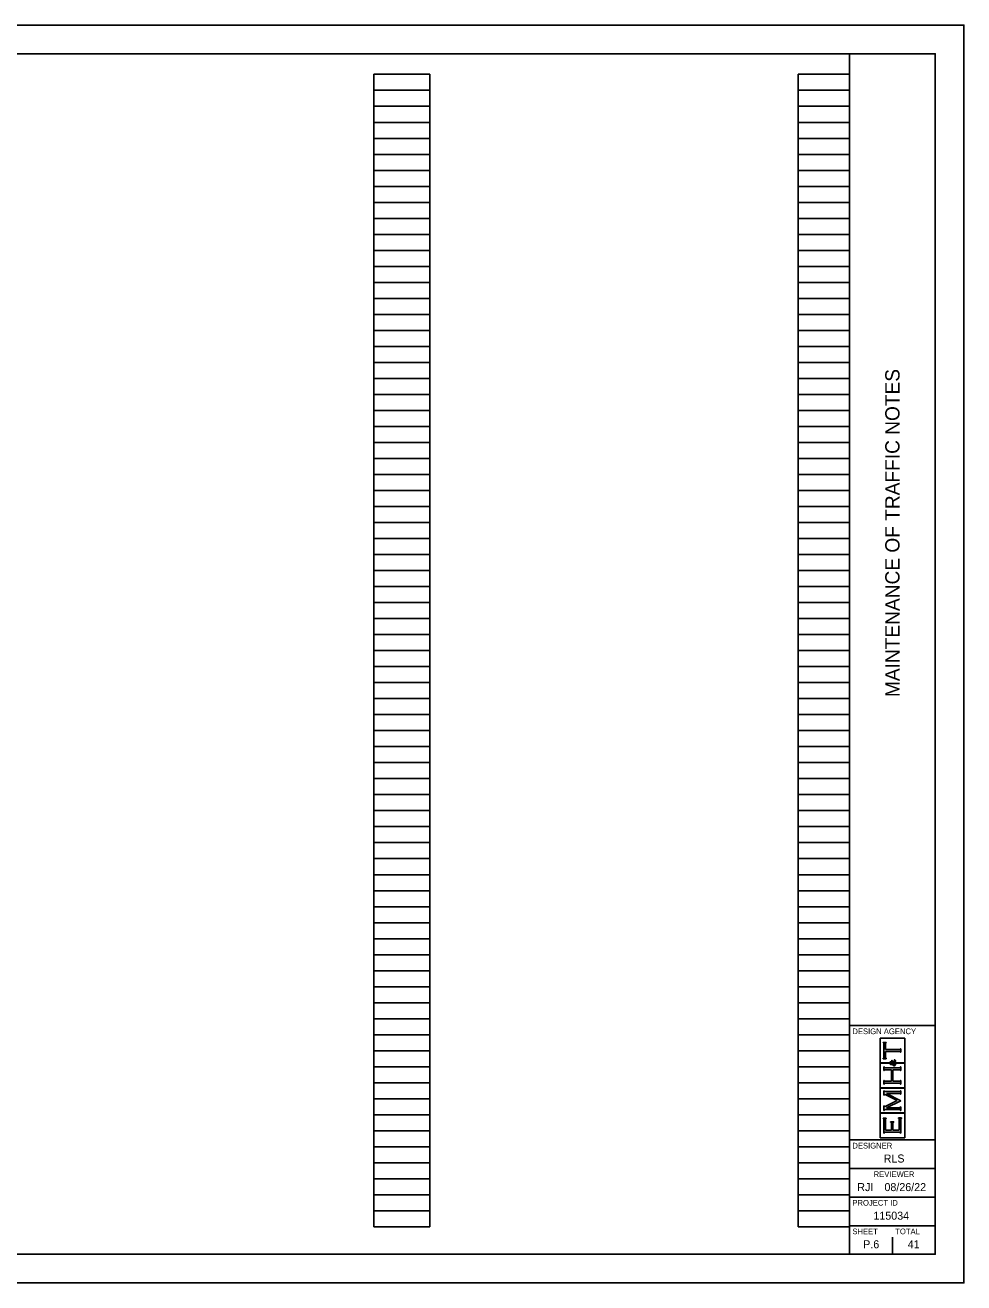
# Model space of a CAD drawing. Extents: x 0 to 34, y 0 to 22.
# Drawn here: x 17.58 to 34, y 0 to 22 of the extents above; entities that cross this region are included whole.
import ezdxf

# ---------------------------------------------------------------- set-up
doc = ezdxf.new("R2010")
doc.units = 0
for name, color, linetype in [('SH_Border', 7, 'Continuous'), ('SH_Cut_Line', 7, 'Continuous'), ('SH_Data', 7, 'Continuous')]:
    doc.layers.add(name, color=color, linetype=linetype)

msp = doc.modelspace()

# ---------------------------------------------------------------- linework, layer by layer
at = {"layer": 'SH_Border'}
for p, q in [((32, 0.5), (32, 21.5)), ((32, 4.5), (33.5, 4.5)), ((32, 2.5), (33.5, 2.5)), ((32, 2), (33.5, 2)), ((32, 1.5), (33.5, 1.5)), ((32, 1), (33.5, 1))]:
    msp.add_line(p, q, dxfattribs=at)
msp.add_lwpolyline([(1.5, 21.5), (33.5, 21.5), (33.5, 0.5), (1.5, 0.5)], close=True, dxfattribs=at)
at = {"layer": 'SH_Cut_Line'}
msp.add_lwpolyline([(0, 0), (34, 0), (34, 22), (0, 22)], close=True, dxfattribs=at)
at = {"layer": 'SH_Data'}
for p, q in [((23.68, 0.98), (23.68, 21.14)), ((23.68, 21.14), (24.66, 21.14)), ((24.66, 0.98), (24.66, 21.14)), ((31.1, 0.98), (31.1, 21.14)), ((31.1, 21.14), (32, 21.14)), ((32, 0.98), (32, 21.14)), ((23.68, 20.86), (24.66, 20.86)), ((31.1, 20.86), (32, 20.86)), ((23.68, 20.58), (24.66, 20.58)), ((31.1, 20.58), (32, 20.58)), ((23.68, 20.3), (24.66, 20.3)), ((31.1, 20.3), (32, 20.3)), ((23.68, 20.02), (24.66, 20.02)), ((31.1, 20.02), (32, 20.02)), ((23.68, 19.74), (24.66, 19.74)), ((31.1, 19.74), (32, 19.74)), ((23.68, 19.46), (24.66, 19.46)), ((31.1, 19.46), (32, 19.46)), ((23.68, 19.18), (24.66, 19.18)), ((31.1, 19.18), (32, 19.18)), ((23.68, 18.9), (24.66, 18.9)), ((31.1, 18.9), (32, 18.9)), ((23.68, 18.62), (24.66, 18.62)), ((31.1, 18.62), (32, 18.62)), ((23.68, 18.34), (24.66, 18.34)), ((31.1, 18.34), (32, 18.34)), ((23.68, 18.06), (24.66, 18.06)), ((31.1, 18.06), (32, 18.06)), ((23.68, 17.78), (24.66, 17.78)), ((31.1, 17.78), (32, 17.78)), ((23.68, 17.5), (24.66, 17.5)), ((31.1, 17.5), (32, 17.5)), ((23.68, 17.22), (24.66, 17.22)), ((31.1, 17.22), (32, 17.22)), ((23.68, 16.94), (24.66, 16.94)), ((31.1, 16.94), (32, 16.94)), ((23.68, 16.66), (24.66, 16.66)), ((31.1, 16.66), (32, 16.66)), ((23.68, 16.38), (24.66, 16.38)), ((31.1, 16.38), (32, 16.38)), ((23.68, 16.1), (24.66, 16.1)), ((31.1, 16.1), (32, 16.1)), ((23.68, 15.82), (24.66, 15.82)), ((31.1, 15.82), (32, 15.82)), ((23.68, 15.54), (24.66, 15.54)), ((31.1, 15.54), (32, 15.54)), ((23.68, 15.26), (24.66, 15.26)), ((31.1, 15.26), (32, 15.26)), ((23.68, 14.98), (24.66, 14.98)), ((31.1, 14.98), (32, 14.98)), ((23.68, 14.7), (24.66, 14.7)), ((31.1, 14.7), (32, 14.7)), ((23.68, 14.42), (24.66, 14.42)), ((31.1, 14.42), (32, 14.42)), ((23.68, 14.14), (24.66, 14.14)), ((31.1, 14.14), (32, 14.14)), ((23.68, 13.86), (24.66, 13.86)), ((31.1, 13.86), (32, 13.86)), ((23.68, 13.58), (24.66, 13.58)), ((31.1, 13.58), (32, 13.58)), ((23.68, 13.3), (24.66, 13.3)), ((31.1, 13.3), (32, 13.3)), ((23.68, 13.02), (24.66, 13.02)), ((31.1, 13.02), (32, 13.02)), ((23.68, 12.74), (24.66, 12.74)), ((31.1, 12.74), (32, 12.74)), ((23.68, 12.46), (24.66, 12.46)), ((31.1, 12.46), (32, 12.46)), ((23.68, 12.18), (24.66, 12.18)), ((31.1, 12.18), (32, 12.18)), ((23.68, 11.9), (24.66, 11.9)), ((31.1, 11.9), (32, 11.9)), ((23.68, 11.62), (24.66, 11.62)), ((31.1, 11.62), (32, 11.62)), ((23.68, 11.34), (24.66, 11.34)), ((31.1, 11.34), (32, 11.34)), ((23.68, 11.06), (24.66, 11.06)), ((31.1, 11.06), (32, 11.06)), ((23.68, 10.78), (24.66, 10.78)), ((31.1, 10.78), (32, 10.78)), ((23.68, 10.5), (24.66, 10.5)), ((31.1, 10.5), (32, 10.5)), ((23.68, 10.22), (24.66, 10.22)), ((31.1, 10.22), (32, 10.22)), ((23.68, 9.94), (24.66, 9.94)), ((31.1, 9.94), (32, 9.94)), ((23.68, 9.66), (24.66, 9.66)), ((31.1, 9.66), (32, 9.66)), ((23.68, 9.38), (24.66, 9.38)), ((31.1, 9.38), (32, 9.38)), ((23.68, 9.1), (24.66, 9.1)), ((31.1, 9.1), (32, 9.1)), ((23.68, 8.82), (24.66, 8.82)), ((31.1, 8.82), (32, 8.82)), ((23.68, 8.54), (24.66, 8.54)), ((31.1, 8.54), (32, 8.54)), ((23.68, 8.26), (24.66, 8.26)), ((31.1, 8.26), (32, 8.26)), ((23.68, 7.98), (24.66, 7.98)), ((31.1, 7.98), (32, 7.98)), ((23.68, 7.7), (24.66, 7.7)), ((31.1, 7.7), (32, 7.7)), ((23.68, 7.42), (24.66, 7.42)), ((31.1, 7.42), (32, 7.42)), ((23.68, 7.14), (24.66, 7.14)), ((31.1, 7.14), (32, 7.14)), ((23.68, 6.86), (24.66, 6.86)), ((31.1, 6.86), (32, 6.86)), ((23.68, 6.58), (24.66, 6.58)), ((31.1, 6.58), (32, 6.58)), ((23.68, 6.3), (24.66, 6.3)), ((31.1, 6.3), (32, 6.3)), ((23.68, 6.02), (24.66, 6.02)), ((31.1, 6.02), (32, 6.02)), ((23.68, 5.74), (24.66, 5.74)), ((31.1, 5.74), (32, 5.74)), ((23.68, 5.46), (24.66, 5.46)), ((31.1, 5.46), (32, 5.46)), ((23.68, 5.18), (24.66, 5.18)), ((31.1, 5.18), (32, 5.18)), ((23.68, 4.9), (24.66, 4.9)), ((31.1, 4.9), (32, 4.9)), ((23.68, 4.62), (24.66, 4.62)), ((31.1, 4.62), (32, 4.62)), ((23.68, 4.34), (24.66, 4.34)), ((31.1, 4.34), (32, 4.34)), ((32.966, 4.28), (32.534, 4.28)), ((32.534, 4.28), (32.534, 3.848)), ((32.588, 4.199), (32.588, 4.206)), ((32.588, 4.206), (32.644, 4.206)), ((32.594, 4.198), (32.588, 4.199)), ((32.598, 4.196), (32.594, 4.198)), ((32.599, 4.194), (32.598, 4.196)), ((32.601, 4.191), (32.599, 4.194)), ((32.602, 4.187), (32.601, 4.191)), ((32.602, 4.181), (32.602, 4.187)), ((32.602, 3.947), (32.602, 4.181)), ((32.632, 4.191), (32.631, 4.187)), ((32.631, 4.187), (32.631, 4.181)), ((32.631, 4.181), (32.631, 4.081)), ((32.633, 4.194), (32.632, 4.191)), ((32.635, 4.196), (32.633, 4.194)), ((32.639, 4.198), (32.635, 4.196)), ((32.644, 4.199), (32.639, 4.198)), ((32.644, 4.206), (32.644, 4.199)), ((32.966, 3.848), (32.966, 4.28)), ((23.68, 4.06), (24.66, 4.06)), ((31.1, 4.06), (32, 4.06)), ((32.631, 4.081), (32.872, 4.081)), ((32.872, 4.047), (32.631, 4.047)), ((32.631, 4.047), (32.631, 3.947)), ((32.872, 4.081), (32.878, 4.081)), ((32.878, 4.047), (32.872, 4.047)), ((32.878, 4.081), (32.882, 4.082)), ((32.883, 4.046), (32.878, 4.047)), ((32.882, 4.082), (32.885, 4.084)), ((32.885, 4.044), (32.883, 4.046)), ((32.885, 4.084), (32.887, 4.085)), ((32.888, 4.042), (32.885, 4.044)), ((32.887, 4.085), (32.889, 4.089)), ((32.889, 4.039), (32.888, 4.042)), ((32.889, 4.089), (32.891, 4.095)), ((32.891, 4.033), (32.889, 4.039)), ((32.891, 4.095), (32.898, 4.095)), ((32.898, 4.033), (32.891, 4.033)), ((32.898, 4.095), (32.898, 4.033)), ((23.68, 3.78), (24.66, 3.78)), ((31.1, 3.78), (32, 3.78)), ((32.534, 3.848), (32.693, 3.848)), ((32.693, 3.842), (32.534, 3.842)), ((32.534, 3.842), (32.534, 3.41)), ((32.588, 3.928), (32.594, 3.93)), ((32.588, 3.921), (32.588, 3.928)), ((32.644, 3.921), (32.588, 3.921)), ((32.594, 3.93), (32.598, 3.932)), ((32.598, 3.932), (32.599, 3.934)), ((32.599, 3.934), (32.601, 3.937)), ((32.601, 3.937), (32.602, 3.941)), ((32.602, 3.941), (32.602, 3.947)), ((32.602, 3.714), (32.602, 3.776)), ((32.602, 3.776), (32.609, 3.776)), ((32.609, 3.776), (32.611, 3.77)), ((32.611, 3.77), (32.612, 3.766)), ((32.612, 3.766), (32.615, 3.765)), ((32.615, 3.765), (32.617, 3.763)), ((32.617, 3.763), (32.622, 3.762)), ((32.622, 3.762), (32.628, 3.762)), ((32.628, 3.762), (32.872, 3.762)), ((32.631, 3.947), (32.631, 3.941)), ((32.631, 3.941), (32.632, 3.937)), ((32.632, 3.937), (32.633, 3.934)), ((32.633, 3.934), (32.635, 3.932)), ((32.635, 3.932), (32.639, 3.93)), ((32.639, 3.93), (32.644, 3.928)), ((32.644, 3.928), (32.644, 3.921)), ((32.693, 3.848), (32.693, 3.842)), ((32.701, 3.852), (32.703, 3.857)), ((32.701, 3.846), (32.701, 3.852)), ((32.701, 3.84), (32.701, 3.846)), ((32.703, 3.835), (32.701, 3.84)), ((32.703, 3.857), (32.706, 3.861)), ((32.706, 3.83), (32.703, 3.835)), ((32.706, 3.861), (32.71, 3.864)), ((32.707, 3.852), (32.706, 3.849)), ((32.706, 3.849), (32.706, 3.846)), ((32.706, 3.846), (32.706, 3.842)), ((32.706, 3.842), (32.708, 3.839)), ((32.71, 3.824), (32.706, 3.83)), ((32.71, 3.854), (32.707, 3.852)), ((32.708, 3.839), (32.711, 3.837)), ((32.71, 3.864), (32.714, 3.866)), ((32.712, 3.856), (32.71, 3.854)), ((32.717, 3.821), (32.71, 3.824)), ((32.711, 3.837), (32.714, 3.835)), ((32.715, 3.857), (32.712, 3.856)), ((32.714, 3.866), (32.719, 3.866)), ((32.714, 3.835), (32.716, 3.834)), ((32.718, 3.857), (32.715, 3.857)), ((32.716, 3.834), (32.719, 3.834)), ((32.725, 3.821), (32.717, 3.821)), ((32.723, 3.857), (32.718, 3.857)), ((32.719, 3.866), (32.724, 3.866)), ((32.719, 3.834), (32.722, 3.834)), ((32.722, 3.834), (32.724, 3.834)), ((32.727, 3.856), (32.723, 3.857)), ((32.724, 3.866), (32.728, 3.864)), ((32.724, 3.834), (32.727, 3.835)), ((32.728, 3.821), (32.725, 3.821)), ((32.73, 3.853), (32.727, 3.856)), ((32.727, 3.835), (32.73, 3.836)), ((32.728, 3.864), (32.732, 3.861)), ((32.731, 3.822), (32.728, 3.821)), ((32.734, 3.85), (32.73, 3.853)), ((32.73, 3.836), (32.734, 3.837)), ((32.734, 3.822), (32.731, 3.822)), ((32.732, 3.861), (32.736, 3.857)), ((32.737, 3.845), (32.734, 3.85)), ((32.734, 3.837), (32.74, 3.839)), ((32.737, 3.823), (32.734, 3.822)), ((32.736, 3.857), (32.74, 3.851)), ((32.74, 3.839), (32.737, 3.845)), ((32.741, 3.825), (32.737, 3.823)), ((32.738, 3.867), (32.738, 3.898)), ((32.738, 3.898), (32.741, 3.898)), ((32.741, 3.867), (32.738, 3.867)), ((32.74, 3.851), (32.745, 3.842)), ((32.741, 3.898), (32.741, 3.894)), ((32.741, 3.894), (32.742, 3.891)), ((32.742, 3.871), (32.741, 3.869)), ((32.741, 3.869), (32.741, 3.867)), ((32.746, 3.827), (32.741, 3.825)), ((32.742, 3.891), (32.744, 3.889)), ((32.743, 3.872), (32.742, 3.871)), ((32.745, 3.873), (32.743, 3.872)), ((32.744, 3.889), (32.745, 3.887)), ((32.745, 3.887), (32.75, 3.883)), ((32.747, 3.874), (32.745, 3.873)), ((32.745, 3.842), (32.755, 3.848)), ((32.753, 3.815), (32.746, 3.827)), ((32.749, 3.874), (32.747, 3.874)), ((32.756, 3.874), (32.749, 3.874)), ((32.75, 3.883), (32.757, 3.879)), ((32.757, 3.832), (32.751, 3.829)), ((32.751, 3.829), (32.755, 3.824)), ((32.759, 3.808), (32.753, 3.815)), ((32.755, 3.848), (32.765, 3.855)), ((32.755, 3.824), (32.758, 3.819)), ((32.764, 3.87), (32.756, 3.874)), ((32.757, 3.879), (32.765, 3.875)), ((32.762, 3.835), (32.757, 3.832)), ((32.758, 3.819), (32.762, 3.817)), ((32.765, 3.803), (32.759, 3.808)), ((32.766, 3.838), (32.762, 3.835)), ((32.762, 3.817), (32.766, 3.814)), ((32.775, 3.861), (32.764, 3.87)), ((32.765, 3.875), (32.772, 3.87)), ((32.765, 3.855), (32.775, 3.861)), ((32.77, 3.799), (32.765, 3.803)), ((32.77, 3.84), (32.766, 3.838)), ((32.766, 3.814), (32.771, 3.812)), ((32.776, 3.845), (32.77, 3.84)), ((32.776, 3.797), (32.77, 3.799)), ((32.771, 3.812), (32.775, 3.812)), ((32.772, 3.87), (32.779, 3.865)), ((32.775, 3.812), (32.78, 3.812)), ((32.785, 3.851), (32.776, 3.845)), ((32.782, 3.797), (32.776, 3.797)), ((32.779, 3.865), (32.784, 3.869)), ((32.78, 3.812), (32.785, 3.814)), ((32.781, 3.9), (32.783, 3.902)), ((32.785, 3.899), (32.781, 3.9)), ((32.788, 3.797), (32.782, 3.797)), ((32.783, 3.902), (32.79, 3.901)), ((32.784, 3.869), (32.787, 3.873)), ((32.788, 3.897), (32.785, 3.899)), ((32.789, 3.846), (32.785, 3.851)), ((32.785, 3.814), (32.789, 3.817)), ((32.787, 3.873), (32.789, 3.876)), ((32.789, 3.895), (32.788, 3.897)), ((32.793, 3.8), (32.788, 3.797)), ((32.791, 3.892), (32.789, 3.895)), ((32.789, 3.876), (32.791, 3.88)), ((32.794, 3.859), (32.789, 3.855)), ((32.789, 3.855), (32.795, 3.849)), ((32.792, 3.842), (32.789, 3.846)), ((32.789, 3.817), (32.793, 3.821)), ((32.79, 3.901), (32.795, 3.898)), ((32.792, 3.89), (32.791, 3.892)), ((32.791, 3.88), (32.792, 3.883)), ((32.792, 3.886), (32.792, 3.89)), ((32.792, 3.883), (32.792, 3.886)), ((32.793, 3.839), (32.792, 3.842)), ((32.794, 3.837), (32.793, 3.839)), ((32.793, 3.821), (32.795, 3.825)), ((32.797, 3.804), (32.793, 3.8)), ((32.798, 3.864), (32.794, 3.859)), ((32.795, 3.834), (32.794, 3.837)), ((32.795, 3.898), (32.799, 3.894)), ((32.795, 3.849), (32.798, 3.843)), ((32.795, 3.831), (32.795, 3.834)), ((32.795, 3.825), (32.795, 3.831)), ((32.801, 3.809), (32.797, 3.804)), ((32.8, 3.868), (32.798, 3.864)), ((32.798, 3.843), (32.8, 3.839)), ((32.799, 3.894), (32.802, 3.89)), ((32.802, 3.872), (32.8, 3.868)), ((32.8, 3.839), (32.802, 3.834)), ((32.803, 3.815), (32.801, 3.809)), ((32.802, 3.89), (32.803, 3.885)), ((32.803, 3.876), (32.802, 3.872)), ((32.802, 3.834), (32.803, 3.829)), ((32.803, 3.885), (32.803, 3.88)), ((32.803, 3.88), (32.803, 3.876)), ((32.807, 3.842), (32.803, 3.848)), ((32.803, 3.848), (32.966, 3.848)), ((32.803, 3.829), (32.803, 3.823)), ((32.803, 3.823), (32.803, 3.815)), ((32.966, 3.842), (32.807, 3.842)), ((32.872, 3.762), (32.878, 3.762)), ((32.878, 3.762), (32.882, 3.763)), ((32.882, 3.763), (32.885, 3.765)), ((32.885, 3.765), (32.887, 3.766)), ((32.887, 3.766), (32.889, 3.77)), ((32.889, 3.77), (32.891, 3.776)), ((32.891, 3.776), (32.898, 3.776)), ((32.898, 3.776), (32.898, 3.714)), ((32.966, 3.41), (32.966, 3.842)), ((32.609, 3.714), (32.602, 3.714)), ((32.602, 3.477), (32.602, 3.538)), ((32.602, 3.538), (32.609, 3.538)), ((32.61, 3.72), (32.609, 3.714)), ((32.609, 3.538), (32.611, 3.533)), ((32.612, 3.723), (32.61, 3.72)), ((32.611, 3.533), (32.612, 3.529)), ((32.615, 3.725), (32.612, 3.723)), ((32.612, 3.529), (32.615, 3.527)), ((32.617, 3.727), (32.615, 3.725)), ((32.615, 3.527), (32.617, 3.526)), ((32.622, 3.728), (32.617, 3.727)), ((32.617, 3.526), (32.622, 3.525)), ((32.628, 3.728), (32.622, 3.728)), ((32.622, 3.525), (32.628, 3.525)), ((32.732, 3.728), (32.628, 3.728)), ((32.628, 3.525), (32.732, 3.525)), ((32.732, 3.525), (32.732, 3.728)), ((32.872, 3.728), (32.76, 3.728)), ((32.76, 3.728), (32.76, 3.525)), ((32.76, 3.525), (32.872, 3.525)), ((32.878, 3.728), (32.872, 3.728)), ((32.872, 3.525), (32.878, 3.525)), ((32.883, 3.727), (32.878, 3.728)), ((32.878, 3.525), (32.883, 3.525)), ((32.885, 3.725), (32.883, 3.727)), ((32.883, 3.525), (32.885, 3.527)), ((32.888, 3.723), (32.885, 3.725)), ((32.885, 3.527), (32.888, 3.529)), ((32.889, 3.72), (32.888, 3.723)), ((32.888, 3.529), (32.889, 3.533)), ((32.891, 3.714), (32.889, 3.72)), ((32.889, 3.533), (32.891, 3.538)), ((32.898, 3.714), (32.891, 3.714)), ((32.891, 3.538), (32.898, 3.538)), ((32.898, 3.538), (32.898, 3.477)), ((23.68, 3.5), (24.66, 3.5)), ((31.1, 3.5), (32, 3.5)), ((32.534, 3.41), (32.966, 3.41)), ((32.966, 3.405), (32.534, 3.405)), ((32.534, 3.405), (32.534, 2.973)), ((32.609, 3.477), (32.602, 3.477)), ((32.602, 3.283), (32.602, 3.36)), ((32.602, 3.36), (32.609, 3.36)), ((32.61, 3.482), (32.609, 3.477)), ((32.609, 3.36), (32.611, 3.354)), ((32.612, 3.486), (32.61, 3.482)), ((32.611, 3.354), (32.612, 3.351)), ((32.615, 3.488), (32.612, 3.486)), ((32.612, 3.351), (32.615, 3.349)), ((32.617, 3.49), (32.615, 3.488)), ((32.615, 3.349), (32.617, 3.347)), ((32.622, 3.491), (32.617, 3.49)), ((32.617, 3.347), (32.622, 3.346)), ((32.628, 3.491), (32.622, 3.491)), ((32.622, 3.346), (32.628, 3.346)), ((32.872, 3.491), (32.628, 3.491)), ((32.628, 3.346), (32.872, 3.346)), ((32.872, 3.312), (32.649, 3.312)), ((32.649, 3.312), (32.898, 3.186)), ((32.75, 3.5), (32.75, 3.5)), ((32.878, 3.491), (32.872, 3.491)), ((32.872, 3.346), (32.878, 3.346)), ((32.878, 3.312), (32.872, 3.312)), ((32.883, 3.49), (32.878, 3.491)), ((32.878, 3.346), (32.882, 3.347)), ((32.883, 3.311), (32.878, 3.312)), ((32.882, 3.347), (32.885, 3.349)), ((32.885, 3.488), (32.883, 3.49)), ((32.885, 3.31), (32.883, 3.311)), ((32.887, 3.486), (32.885, 3.488)), ((32.885, 3.349), (32.887, 3.351)), ((32.887, 3.308), (32.885, 3.31)), ((32.887, 3.351), (32.889, 3.354)), ((32.889, 3.304), (32.887, 3.308)), ((32.889, 3.482), (32.887, 3.486)), ((32.891, 3.477), (32.889, 3.482)), ((32.889, 3.354), (32.891, 3.36)), ((32.891, 3.298), (32.889, 3.304)), ((32.898, 3.477), (32.891, 3.477)), ((32.891, 3.36), (32.898, 3.36)), ((32.898, 3.36), (32.898, 3.298)), ((32.966, 2.973), (32.966, 3.405)), ((23.68, 3.22), (24.66, 3.22)), ((31.1, 3.22), (32, 3.22)), ((32.609, 3.283), (32.602, 3.283)), ((32.602, 3.017), (32.602, 3.094)), ((32.602, 3.094), (32.609, 3.094)), ((32.612, 3.29), (32.609, 3.283)), ((32.609, 3.094), (32.612, 3.087)), ((32.615, 3.293), (32.612, 3.29)), ((32.612, 3.087), (32.615, 3.083)), ((32.618, 3.293), (32.615, 3.293)), ((32.615, 3.083), (32.618, 3.083)), ((32.621, 3.293), (32.618, 3.293)), ((32.618, 3.083), (32.62, 3.083)), ((32.62, 3.083), (32.625, 3.086)), ((32.626, 3.292), (32.621, 3.293)), ((32.625, 3.086), (32.635, 3.09)), ((32.633, 3.288), (32.626, 3.292)), ((32.831, 3.189), (32.633, 3.288)), ((32.635, 3.09), (32.831, 3.189)), ((32.898, 3.186), (32.649, 3.062)), ((32.898, 3.298), (32.891, 3.298)), ((23.68, 2.94), (24.66, 2.94)), ((31.1, 2.94), (32, 2.94)), ((32.534, 2.973), (32.966, 2.973)), ((32.966, 2.967), (32.534, 2.967)), ((32.534, 2.967), (32.534, 2.535)), ((32.588, 2.874), (32.588, 2.881)), ((32.588, 2.881), (32.644, 2.881)), ((32.594, 2.873), (32.588, 2.874)), ((32.598, 2.871), (32.594, 2.873)), ((32.599, 2.868), (32.598, 2.871)), ((32.601, 2.866), (32.599, 2.868)), ((32.602, 2.862), (32.601, 2.866)), ((32.609, 3.017), (32.602, 3.017)), ((32.602, 2.856), (32.602, 2.862)), ((32.61, 3.023), (32.609, 3.017)), ((32.612, 3.026), (32.61, 3.023)), ((32.615, 3.028), (32.612, 3.026)), ((32.617, 3.03), (32.615, 3.028)), ((32.622, 3.031), (32.617, 3.03)), ((32.628, 3.031), (32.622, 3.031)), ((32.872, 3.031), (32.628, 3.031)), ((32.632, 2.866), (32.631, 2.862)), ((32.631, 2.862), (32.631, 2.856)), ((32.633, 2.868), (32.632, 2.866)), ((32.635, 2.871), (32.633, 2.868)), ((32.639, 2.873), (32.635, 2.871)), ((32.644, 2.874), (32.639, 2.873)), ((32.644, 2.881), (32.644, 2.874)), ((32.649, 3.062), (32.872, 3.062)), ((32.855, 2.877), (32.855, 2.884)), ((32.855, 2.884), (32.912, 2.884)), ((32.861, 2.876), (32.855, 2.877)), ((32.865, 2.874), (32.861, 2.876)), ((32.867, 2.872), (32.865, 2.874)), ((32.868, 2.869), (32.867, 2.872)), ((32.869, 2.865), (32.868, 2.869)), ((32.869, 2.859), (32.869, 2.865)), ((32.872, 3.062), (32.878, 3.062)), ((32.878, 3.031), (32.872, 3.031)), ((32.878, 3.062), (32.882, 3.063)), ((32.883, 3.03), (32.878, 3.031)), ((32.882, 3.063), (32.885, 3.065)), ((32.885, 3.028), (32.883, 3.03)), ((32.885, 3.065), (32.887, 3.067)), ((32.887, 3.026), (32.885, 3.028)), ((32.887, 3.067), (32.889, 3.07)), ((32.889, 3.023), (32.887, 3.026)), ((32.889, 3.07), (32.891, 3.076)), ((32.891, 3.017), (32.889, 3.023)), ((32.891, 3.076), (32.898, 3.076)), ((32.898, 3.017), (32.891, 3.017)), ((32.898, 3.076), (32.898, 3.017)), ((32.899, 2.869), (32.898, 2.865)), ((32.898, 2.865), (32.898, 2.858)), ((32.901, 2.871), (32.899, 2.869)), ((32.903, 2.874), (32.901, 2.871)), ((32.906, 2.876), (32.903, 2.874)), ((32.912, 2.877), (32.906, 2.876)), ((32.912, 2.884), (32.912, 2.877)), ((32.966, 2.535), (32.966, 2.967)), ((23.68, 2.66), (24.66, 2.66)), ((31.1, 2.66), (32, 2.66)), ((32.602, 2.621), (32.602, 2.856)), ((32.631, 2.856), (32.631, 2.669)), ((32.631, 2.669), (32.732, 2.669)), ((32.718, 2.81), (32.718, 2.816)), ((32.718, 2.816), (32.774, 2.816)), ((32.723, 2.808), (32.718, 2.81)), ((32.727, 2.806), (32.723, 2.808)), ((32.729, 2.804), (32.727, 2.806)), ((32.731, 2.801), (32.729, 2.804)), ((32.732, 2.797), (32.731, 2.801)), ((32.732, 2.791), (32.732, 2.797)), ((32.732, 2.669), (32.732, 2.791)), ((32.761, 2.801), (32.76, 2.797)), ((32.76, 2.797), (32.76, 2.791)), ((32.76, 2.791), (32.76, 2.669)), ((32.76, 2.669), (32.869, 2.669)), ((32.763, 2.804), (32.761, 2.801)), ((32.765, 2.806), (32.763, 2.804)), ((32.768, 2.808), (32.765, 2.806)), ((32.774, 2.81), (32.768, 2.808)), ((32.774, 2.816), (32.774, 2.81)), ((32.869, 2.669), (32.869, 2.859)), ((32.898, 2.858), (32.898, 2.621)), ((32.534, 2.535), (32.966, 2.535)), ((32.609, 2.621), (32.602, 2.621)), ((32.611, 2.626), (32.609, 2.621)), ((32.612, 2.63), (32.611, 2.626)), ((32.615, 2.632), (32.612, 2.63)), ((32.617, 2.634), (32.615, 2.632)), ((32.622, 2.635), (32.617, 2.634)), ((32.628, 2.635), (32.622, 2.635)), ((32.872, 2.635), (32.628, 2.635)), ((32.878, 2.635), (32.872, 2.635)), ((32.883, 2.634), (32.878, 2.635)), ((32.885, 2.632), (32.883, 2.634)), ((32.887, 2.63), (32.885, 2.632)), ((32.889, 2.627), (32.887, 2.63)), ((32.891, 2.621), (32.889, 2.627)), ((32.898, 2.621), (32.891, 2.621)), ((23.68, 2.38), (24.66, 2.38)), ((31.1, 2.38), (32, 2.38)), ((23.68, 2.1), (24.66, 2.1)), ((31.1, 2.1), (32, 2.1)), ((23.68, 1.82), (24.66, 1.82)), ((31.1, 1.82), (32, 1.82)), ((23.68, 1.54), (24.66, 1.54)), ((31.1, 1.54), (32, 1.54)), ((23.68, 1.26), (24.66, 1.26)), ((31.1, 1.26), (32, 1.26)), ((23.68, 0.98), (24.66, 0.98)), ((31.1, 0.98), (32, 0.98)), ((32.375, 0.675), (32.375, 0.675)), ((32.75, 0.5), (32.75, 0.8))]:
    msp.add_line(p, q, dxfattribs=at)

# ---------------------------------------------------------------- texts
msp.add_text('MAINTENANCE OF TRAFFIC NOTES', height=0.25, rotation=90, dxfattribs=at).set_placement((32.875, 10.247))
for s, height, p in [('DESIGN AGENCY', 0.1, (32.05, 4.35)), ('DESIGNER', 0.1, (32.05, 2.35)), ('RLS', 0.14, (32.597, 2.105)), ('REVIEWER', 0.1, (32.422, 1.85)), ('RJI', 0.14, (32.136, 1.605)), ('08/26/22', 0.14, (32.611, 1.605)), ('PROJECT ID', 0.1, (32.05, 1.35)), ('115034', 0.14, (32.418, 1.105)), ('SHEET', 0.1, (32.05, 0.85)), ('TOTAL', 0.1, (32.8, 0.85)), ('P.6', 0.14, (32.239, 0.605)), ('41', 0.14, (33.019, 0.605))]:
    msp.add_text(s, height=height, dxfattribs=at).set_placement(p)

doc.saveas('drawing.dxf')
